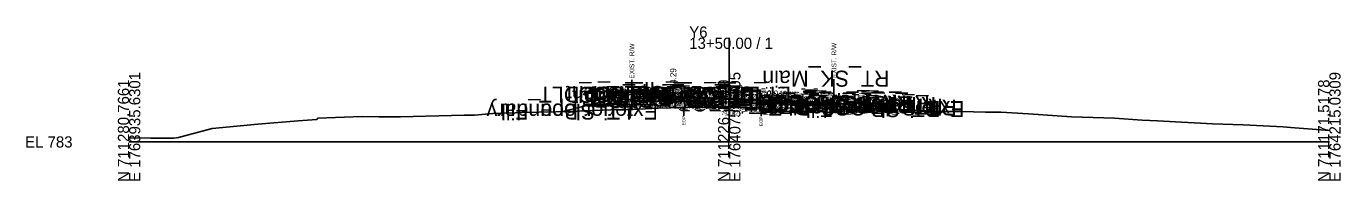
# Model space of a CAD drawing. Extents: x -26 to 1764234, y -10 to 711417.
# Drawn here: x -25.7 to 302.8, y 3490.3 to 3528.9 of the extents above; entities that cross this region are included whole.
import ezdxf

# ---------------------------------------------------------------- set-up
doc = ezdxf.new("R2010")
doc.units = 0
for name, color, linetype in [('Default', 7, 'Continuous'), ('Exist Cross Section Cell', 7, 'Continuous'), ('Exist XS Center Line Elevation Label', 7, 'Continuous'), ('Exist XS Ground Line', 7, 'Continuous'), ('Old_Level_10', 7, 'Continuous'), ('Prop CMT Conc Surface', 7, 'Continuous'), ('Prop CMT Concrete Structures', 7, 'Continuous'), ('Prop CMT Pvmt Course 1', 7, 'Continuous'), ('Prop CMT Pvmt Course 1 CG', 7, 'Continuous'), ('Prop CMT Pvmt Course 2', 7, 'Continuous'), ('Prop CMT Pvmt Course 3', 7, 'Continuous'), ('Prop CMT Pvmt Surface', 7, 'Continuous'), ('Prop CMT Pvmt Surface Shoulder', 7, 'Continuous'), ('Prop CMT Shld Paved Course 1', 7, 'Continuous'), ('Prop CMT Shld Paved Course 2', 7, 'Continuous'), ('Prop CMT Shld Paved Course 3', 7, 'Continuous'), ('Prop CMT Slope Grass', 7, 'Continuous'), ('Prop CMT Subgrade Earthwork', 7, 'Continuous'), ('Prop XS Earthwork Shape', 7, 'Continuous'), ('Prop XS Hydro Elevations', 7, 'Continuous'), ('Prop XS SE Text', 7, 'Continuous'), ('Prop XS Side Slope Text', 7, 'Continuous'), ('Scratch_Level_7', 7, 'Continuous')]:
    doc.layers.add(name, color=color, linetype=linetype)

msp = doc.modelspace()

# ---------------------------------------------------------------- linework, layer by layer
at = {"layer": 'Exist Cross Section Cell'}
for p, q in [((150, 3500), (150, 3526.05)), ((0, 3500), (150, 3500)), ((150, 3500), (300, 3500))]:
    msp.add_line(p, q, dxfattribs=at)
at = {"layer": 'Exist XS Ground Line'}
msp.add_lwpolyline([(0, 3500.98), (5.4, 3500.9), (11.15, 3500.9), (12.33, 3501.11), (20.77, 3503.37), (32.2, 3504.42), (42.25, 3505.28), (46.89, 3505.57), (47.14, 3505.93), (58.22, 3506.38), (62.39, 3506.27), (67.83, 3506.23), (83.79, 3506.71), (86.37, 3506.68), (90.92, 3507.07), (96.59, 3507.3), (98.23, 3507.32), (106.68, 3507.55), (112.03, 3507.66), (120.37, 3508.01), (125.87, 3508.11), (132.26, 3508.42), (138.67, 3508.59), (139.13, 3508.62), (139.72, 3508.65), (140.25, 3508.66), (143, 3508.68), (145.62, 3508.66), (146.29, 3508.68), (146.77, 3508.67), (147.41, 3508.65), (147.94, 3508.64), (150, 3508.62), (150.63, 3508.62), (150.99, 3508.61), (151.81, 3508.6), (153.67, 3508.56), (156.4, 3508.54), (157.28, 3508.51), (157.96, 3508.46), (165.67, 3507.47), (166.81, 3507.33), (167.86, 3507.52), (172.44, 3508.52), (176.88, 3508.22), (177.96, 3508.07), (186.68, 3508.23), (189.67, 3508.26), (190.93, 3508.16), (203.33, 3507.59), (208.09, 3507.62), (214.07, 3507.44), (217.91, 3507.4), (224.81, 3507), (235.55, 3506.29), (246.29, 3505.94), (253.18, 3505.41), (257.02, 3505.25), (263.02, 3504.91), (267.76, 3504.7), (270.81, 3504.53), (278.5, 3504.23), (288.44, 3503.8), (289.38, 3503.72), (290.25, 3503.64), (300, 3502.82)], dxfattribs=at)
at = {"layer": 'Old_Level_10'}
for p, q in [((125.67, 3515.5), (125.67, 3508.1)), ((176.19, 3515.67), (176.19, 3508.27)), ((138.67, 3508.59), (138.67, 3506.54)), ((157.96, 3508.46), (157.96, 3506.41))]:
    msp.add_line(p, q, dxfattribs=at)
at = {"layer": 'Prop CMT Conc Surface'}
for points in [[(136, 3511.29), (136, 3511.79), (135.5, 3511.79)], [(138, 3511.29), (136, 3511.29)]]:
    msp.add_lwpolyline(points, dxfattribs=at)
at = {"layer": 'Prop CMT Concrete Structures'}
for points in [[(138, 3511.29), (136, 3511.29), (136, 3511.79), (135.5, 3511.79)], [(135.5, 3511.79), (135.5, 3510.81), (138, 3510.71)], [(138, 3510.71), (138, 3511.29)]]:
    msp.add_lwpolyline(points, dxfattribs=at)
at = {"layer": 'Prop CMT Pvmt Course 1'}
for points in [[(150, 3510.81), (138, 3511.29)], [(138, 3511.29), (138, 3511.04)], [(138, 3511.04), (138.67, 3511.02)], [(138.67, 3511.02), (138.67, 3511.02)], [(138.67, 3511.02), (150, 3510.56)], [(150, 3510.56), (150, 3510.81)], [(150, 3510.81), (174, 3509.85)], [(150, 3510.56), (150, 3510.56), (150, 3510.56)], [(157.96, 3510.25), (150, 3510.56)], [(174, 3509.6), (157.96, 3510.25)], [(157.96, 3510.25), (157.96, 3510.25)], [(174, 3509.85), (174, 3509.6)]]:
    msp.add_lwpolyline(points, dxfattribs=at)
at = {"layer": 'Prop CMT Pvmt Course 1 CG'}
for points in [[(138, 3510.71), (135, 3510.83), (134.72, 3510.55)], [(134.72, 3510.55), (138, 3510.42)], [(138, 3510.42), (138, 3510.71)]]:
    msp.add_lwpolyline(points, dxfattribs=at)
at = {"layer": 'Prop CMT Pvmt Course 2'}
for points in [[(138.67, 3511.02), (138, 3511.04)], [(138, 3511.04), (138, 3510.79)], [(138, 3510.79), (138.67, 3510.77)], [(138.67, 3510.77), (138.67, 3511.02)], [(157.96, 3510), (157.96, 3510.25)], [(157.96, 3510.25), (174, 3509.6)], [(174, 3509.35), (157.96, 3510)], [(174, 3509.6), (174, 3509.35)]]:
    msp.add_lwpolyline(points, dxfattribs=at)
at = {"layer": 'Prop CMT Pvmt Course 3'}
for points in [[(138.67, 3510.77), (138, 3510.79)], [(138, 3510.79), (138, 3510.42)], [(138, 3510.42), (138.67, 3510.39)], [(138.67, 3510.39), (138.67, 3510.77)], [(157.96, 3510), (174, 3509.35)], [(157.96, 3509.62), (157.96, 3510)], [(174, 3508.98), (157.96, 3509.62)], [(174, 3509.35), (174, 3508.98)]]:
    msp.add_lwpolyline(points, dxfattribs=at)
at = {"layer": 'Prop CMT Pvmt Surface'}
for points in [[(150, 3510.81), (138, 3511.29)], [(150, 3510.81), (174, 3509.85)]]:
    msp.add_lwpolyline(points, dxfattribs=at)
at = {"layer": 'Prop CMT Pvmt Surface Shoulder'}
msp.add_lwpolyline([(174, 3509.85), (176, 3509.77)], dxfattribs=at)
at = {"layer": 'Prop CMT Shld Paved Course 1'}
for points in [[(174, 3509.85), (176, 3509.77), (176.26, 3509.51)], [(174, 3509.6), (174, 3509.85)], [(176.26, 3509.51), (174, 3509.6)]]:
    msp.add_lwpolyline(points, dxfattribs=at)
at = {"layer": 'Prop CMT Shld Paved Course 2'}
for points in [[(174, 3509.6), (176.26, 3509.51), (176.52, 3509.25)], [(174, 3509.35), (174, 3509.6)], [(176.52, 3509.25), (174, 3509.35)]]:
    msp.add_lwpolyline(points, dxfattribs=at)
at = {"layer": 'Prop CMT Shld Paved Course 3'}
for points in [[(174, 3509.35), (176.52, 3509.25), (177.02, 3509.23), (177.41, 3508.84)], [(174, 3508.98), (174, 3509.35)], [(177.41, 3508.84), (174, 3508.98)]]:
    msp.add_lwpolyline(points, dxfattribs=at)
at = {"layer": 'Prop CMT Slope Grass'}
for points in [[(135.5, 3511.79), (126, 3511.98), (108.41, 3507.59)], [(176, 3509.77), (180, 3509.45), (185.01, 3508.2)]]:
    msp.add_lwpolyline(points, dxfattribs=at)
at = {"layer": 'Prop CMT Subgrade Earthwork'}
for points in [[(138, 3510.42), (134.72, 3510.55), (133.43, 3511.84)], [(157.96, 3509.62), (138, 3510.42)], [(157.96, 3509.62), (174, 3508.98)], [(174, 3508.98), (177.41, 3508.84)], [(177.41, 3508.84), (183.4, 3508.6)]]:
    msp.add_lwpolyline(points, dxfattribs=at)
at = {"layer": 'Prop XS Earthwork Shape'}
msp.add_lwpolyline([(153.67, 3508.56), (156.4, 3508.54), (157.28, 3508.51), (157.96, 3508.46), (165.67, 3507.47), (166.81, 3507.33), (167.86, 3507.52), (172.44, 3508.52), (176.88, 3508.22), (177.96, 3508.07), (185.01, 3508.2), (183.4, 3508.6), (177.41, 3508.84), (174, 3508.98), (157.96, 3509.62), (138, 3510.42), (134.72, 3510.55), (133.43, 3511.84), (126, 3511.98), (108.41, 3507.59), (112.03, 3507.66), (120.37, 3508.01), (125.87, 3508.11), (132.26, 3508.42), (138.67, 3508.59), (139.13, 3508.62), (139.72, 3508.65), (140.25, 3508.66), (143, 3508.68), (145.62, 3508.66), (146.29, 3508.68), (146.77, 3508.67), (147.41, 3508.65), (147.94, 3508.64), (150, 3508.62), (150.63, 3508.62), (150.99, 3508.61), (151.81, 3508.6)], close=True, dxfattribs=at)

# ---------------------------------------------------------------- texts
at = {"layer": 'Default'}
msp.add_text('-', height=0.0001, dxfattribs=at).set_placement((0, 3500))
at = {"layer": 'Exist Cross Section Cell'}
for s, p in [('Y6', (140, 3526.05)), ('13+50.00 / 1', (140, 3523.25)), ('EL 783', (-26, 3498.6))]:
    msp.add_text(s, height=2.8, dxfattribs=at).set_placement(p)
for s, p in [('N 711280.7661', (0, 3490)), ('E 1763935.6301', (2.8, 3490)), ('N 711226.1419', (150, 3490)), ('E 1764075.3305', (152.8, 3490)), ('N 711171.5178', (300, 3490)), ('E 1764215.0309', (302.8, 3490))]:
    msp.add_text(s, height=2.8, rotation=90, dxfattribs=at).set_placement(p)
at = {"layer": 'Exist XS Center Line Elevation Label'}
msp.add_text('791.62', height=1, dxfattribs=at).set_placement((148.01, 3506.62))
at = {"layer": 'Old_Level_10'}
for s, height, p in [('EXIST. R/W', 1.181, (126.27, 3515.81)), ('EXIST. R/W', 1.181, (176.78, 3515.97)), ('EOP', 0.787, (139.06, 3504.14)), ('EOP', 0.787, (158.35, 3504.01))]:
    msp.add_text(s, height=height, rotation=90, dxfattribs=at).set_placement(p)
at = {"layer": 'Prop XS Hydro Elevations'}
msp.add_text('794.29', height=1.5, rotation=90, dxfattribs=at).set_placement((136.75, 3512.29))
at = {"layer": 'Prop XS SE Text'}
for p in [(141.42, 3512.16), (159.42, 3511.44)]:
    msp.add_text('0.040', height=1.5, rotation=357.7094, dxfattribs=at).set_placement(p)
at = {"layer": 'Prop XS Side Slope Text'}
for rotation, p in [(14.0362, (115.87, 3510.22)), (345.9638, (181.53, 3509.84))]:
    msp.add_text('4:1', height=1.5, rotation=rotation, dxfattribs=at).set_placement(p)
at = {"layer": 'Scratch_Level_7'}
for s, p in [('RT_SK_Main', (190.06, 3517.81)), ('LT_Sub_Trench_Out_DLT', (165.46, 3513.84)), ('LT_CSLP_Pnt', (143.38, 3513.98)), ('LT_CG1_Shelf_Out', (157.74, 3512.83)), ('LT_CG_Top_BOC', (156.41, 3513.79)), ('LT_CG_Bot_BOC', (155.97, 3512.81)), ('LT_CG_Top_Face', (157.82, 3513.79)), ('LT_CG_Top_Gut', (155.87, 3513.29)), ('LT_Sub_OEOP', (152.91, 3512.55)), ('LT_PV1_OEEOP', (158.37, 3513.02)), ('LT_PV1_OEOT', (155.63, 3513.29)), ('LT_PV2_OEEOP', (159.38, 3513.02)), ('LT_PV3_OEEOP', (159.41, 3512.77)), ('LT_Sub_OEEOP', (158.84, 3512.39)), ('LT_PV2_OEOT', (156.64, 3513.04)), ('LT_PV3_OEOT', (156.67, 3512.79)), ('LT_Sub_OEOT', (156.11, 3512.42)), ('LT_CG_Bot_IE', (155.98, 3512.71)), ('RT_PV1_IEEOP', (169.32, 3512.56)), ('LT_PV1_IEEOP', (168.82, 3512.56)), ('RT_PV2_IEEOP', (170.33, 3512.56)), ('LT_PV2_IEEOP', (169.82, 3512.56)), ('RT_PV1_OEEOP', (178.16, 3512.25)), ('PV1_PGL', (160.68, 3512.81)), ('RT_PV2_OEEOP', (179.17, 3512.25)), ('RT_PV3_OEEOP', (179.2, 3512)), ('RT_Sub_OEEOP', (178.63, 3511.62)), ('PV2_PGL', (161.68, 3512.56)), ('RT_PV1_OEOT', (192.14, 3511.85)), ('RT_PS3_Shelf_Out', (201.71, 3511.23)), ('RT_PV2_OEOT', (193.15, 3511.6)), ('RT_PV3_OEOT', (193.18, 3511.35)), ('RT_Sub_OEOT', (192.61, 3510.98)), ('RT_PS1_OEOP', (194.41, 3511.77)), ('RT_PS2_OEOP', (195.67, 3511.51)), ('RT_PS3_OEOP', (195.97, 3511.25)), ('RT_GS_OS_CTL', (200.12, 3511.45)), ('Exterior Boundary', (132.18, 3509.59)), ('LT_Slope_Fill', (125.68, 3509.59)), ('RT_Sub_Trench_Out', (203.36, 3510.84)), ('RT_Sub_OSS_DLT', (206.86, 3510.6)), ('Exterior Boundary', (208.78, 3510.2)), ('RT_Slope_Fill', (202.78, 3510.2))]:
    msp.add_text(s, height=4, rotation=180, dxfattribs=at).set_placement(p)

doc.saveas('drawing.dxf')
